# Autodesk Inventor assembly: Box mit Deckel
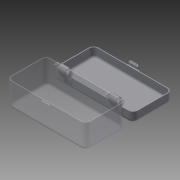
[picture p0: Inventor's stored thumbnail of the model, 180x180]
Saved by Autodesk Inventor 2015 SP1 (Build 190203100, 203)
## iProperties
Created: 2014-11
Part Number: Box mit Deckel
Document SubType Name: Assembly
Designer: Watson
Author: Watson
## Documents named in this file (3)
- C:\Users\Watson\Desktop\Ultimaker\Box mit Deckel\Box mit Deckel.iam
- C:\Users\Watson\Desktop\Ultimaker\Box mit Deckel\Box.ipt
- C:\Users\Watson\Desktop\Ultimaker\Box mit Deckel\Deckel.ipt
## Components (2 placed, 2 different names)
1. Box:1 — Passend:1, Fluchtend:1, Fluchtend:2, Fluchtend:3
2. Deckel:1 — Passend:1, Fluchtend:1, Fluchtend:2, Fluchtend:3
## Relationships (4: Flush 3, Mate 1)
- Passend:1 [Mate]: Box:1 ↔ Deckel:1
- Fluchtend:1 [Flush]: Box:1 ↔ Deckel:1
- Fluchtend:2 [Flush]: Box:1 ↔ Deckel:1
- Fluchtend:3 [Flush]: Box:1 ↔ Deckel:1
